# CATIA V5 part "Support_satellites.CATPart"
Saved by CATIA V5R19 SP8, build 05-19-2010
Part number: Support_satellites
Bounding box of the stored display mesh (mm): x -4 to 32, y -38 to 38, z -38 to 38
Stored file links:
  G:\EU_thinkMotion\CFAO_2010\SIL_groupe2\SIL_groupe2\msauret\Brevet_Sauret_parametre\Support_satellites.CATPart
  F:\Brevet_Sauret paramétré\Product3.CATProduct
  G:\EU_thinkMotion\CFAO_2010\SIL_groupe2\SIL_groupe2\msauret\Brevet_Sauret_parametre\plateau.CATPart
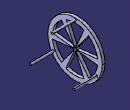
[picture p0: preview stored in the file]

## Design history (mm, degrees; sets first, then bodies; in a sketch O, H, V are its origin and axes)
Set1
  Plane1: linked copy from another document
  Plane2: linked copy from another document
  Line1: linked copy from another document
  Plane3: linked copy from another document
  Plane4: linked copy from another document
Body1 (main body)
  Sketch1 on Plane1, origin (0, 0, 0), H (0, 1, 0), V (0, 0, 1)
    circle A1 centre (0, 0) radius 38
  Pad1: profile Sketch1, direction (1, 0, 0), up to Plane2
  Sketch2 on Plane1, origin (0, 0, 0), H (0, 1, 0), V (0, 0, 1)
    arc A1 centre (0, 0) radius 32 from (12.6054, 29.4126) to (-12.6054, 29.4126) ccw
    line L1 (12.6054, 29.4126) -> (1.1818, 2.7574)
    line L2 (-1.1818, 2.7574) -> (-12.6054, 29.4126)
    arc A2 centre (0, 0) radius 3 from (1.1818, 2.7574) to (-1.1818, 2.7574) ccw
    point P3 (0, 0)
    coincidence: L1 O, P3 L2, P3 V
  Pocket1: profile Sketch2, direction (-1, 0, 0), up to Plane2
  CircPattern1: of Pocket1, instances 6, angular step 60, axis from Line1
  Sketch3 on Plane1, origin (0, 0, 0), H (0, 1, 0), V (0, 0, 1)
    circle A1 centre (0, 0) radius 2
    point P1 (0, 0)
    coincidence: P1 V
  Pocket2: profile Sketch3, direction (-1, 0, 0), up to Plane2
  Sketch4 on Plane1, origin (0, 0, 0), H (0, 1, 0), V (0, 0, 1)
    circle A1 centre (0, 35.1092) radius 1.5
    point P1 (0, 35.1092)
    coincidence: P1 V
  Pad2: profile Sketch4, direction (1, 0, 0), up to Plane4
  CircPattern2: of Pad2, instances 3, angular step 120, axis from Line1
